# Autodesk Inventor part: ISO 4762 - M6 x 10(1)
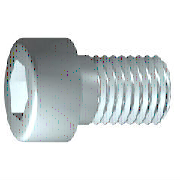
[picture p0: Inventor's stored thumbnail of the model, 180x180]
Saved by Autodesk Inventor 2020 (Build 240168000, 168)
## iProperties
IsCustomPart: 0
Created: 2019-01
Part Number: ISO 4762 - M6 x 10(1)
Material: Nerezová ocel 440C
Description: Šroub s válcovou hlavou s vnitřním šestihranem
Document SubType Name: Modeling
Standard: ISO 4762
Designer: doma
Standard Revision: Fourth edition 2004-03-01
Standards Organization: ISO
Language: cs-CZ
Size Designation: M6 x 10
Categories: <MemberInstance><Categories><Category DisplayName="Spojovací materiál" InternalName="e4da775c-781d-43d5-af7c-5136215cf5a6" Mnemonic="FSTN"><Category DisplayName
Density: 7.75 g/cm^3
Appearance: Pololeštěná
Mass: 5.18675 g
Surface Area: 5.75604 cm^2
Volume: 0.669258 cm^3
Author: doma
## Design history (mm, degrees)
sketch "Náčrt1"
  geometry: L1 (-1.333, 0)-(10, 0); L2 (10, 0)-(10, 3); L3 (10, 3)-(2.5, 3); L4 (2.5, 3)-(1.886, 3); L5 (1.886, 3)-(0, 3); L6 (0, 3)-(0, 5); L7 (0, 5)-(-6, 5); L8 (-6, 5)-(-6, 2.887); L9 (-6, 2.887)-(-3, 2.887); L10 (-3, 2.887)-(-1.333, 0); L11 (-9.2, 0)-(13.2, 0) reference; L12 (0, -1)-(0, 6) reference; L13 (2.5, 3)-(0, 3)
  constraints: 22 end point, 6 parallel, 2 collinear, 2 perpendicular, 1 horizontal, 1 point on line
  dimensions: "d1" = 7.5 distance from line of L3.end L2 (= GEL); "d2" = 0.61355 distance of L4.end L3.end (computed from GAL); "d3" = 6 distance between parallel lines of L8 L6 (= KOH); "d4" = 3 distance of L8.end L9.end (= INTI); "d5" = 60 deg angle of L10 L1; "d6" = 6 diameter of L3 L1 (= GD); "d7" = 6 diameter of L5 L1 (= BDM); "d8" = 5.7735 diameter of L9 L1 (= 1.1547 x SW); "d9" = 10 diameter of L7 L1 (= KOD); "d26" = 10 distance between parallel lines of L12 L2 (= NLG)
revolve "Těleso" sketch "Náčrt1" stored, may be unused: angle "d10" = 90 deg
sketch "Náčrt2"
  geometry: L1 (0, -7)-(0, 7) reference; L2 (-7, 0)-(7, 0) reference; L3 (2.887, 0)-(1.443, -2.5); L4 (1.443, -2.5)-(-1.443, -2.5); L5 (-1.443, -2.5)-(-2.887, 0); L6 (-2.887, 0)-(-1.443, 2.5); L7 (-1.443, 2.5)-(1.443, 2.5); L8 (1.443, 2.5)-(2.887, 0); 2 further points
  constraints: 12 end point, 1 coincident, 1 horizontal alignment, 1 point on line, 12 other
extrude "Drážka" join sketch "Náčrt2" stored distance "d11" = 10; taper "d12" = 0 deg
workplane "Work Plane1"
fillet "Fillet2" dims "d30" = 0.1 (= R)
body "Solid1"
fillet "Zaoblení1" dims "d17" = 0.6 (= RR)
feature "Závit" dims "d13" = 7.5 (= GEL), "d14" = 0
chamfer "Zkosení1" distance "d15" = 0.61345 (= -0.5 x SPD + 0.5 x GD); stored, may be unused: second distance "d16" = 0.61345 (= GUL), angle "d27" = 45 deg
other parameters: "GD" = 6 [user parameter; used in 2 equation terms], "NLG" = 10 [user parameter; used in 1 equation term], "GEL" = 7.5 [user parameter; used in 2 equation terms], "KOD" = 10 [user parameter; used in 1 equation term], "KOH" = 6 [user parameter; used in 1 equation term], "INTI" = 3 [user parameter; used in 1 equation term], "GAL" = 0.61345 (= 0.61345 x PTC) [user parameter; used in 1 equation term], "GUL" = 0.61345 (= 0.61345 x PTC) [user parameter; used in 1 equation term], "BDM" = 6 (= NND) [user parameter; used in 1 equation term], "SW" = 5 [user parameter; used in 2 equation terms], "RR" = 0.6 [user parameter; used in 1 equation term], "SPD" = 4.7731 (= NND - 1.2269 x PTC) [user parameter; used in 1 equation term], "d19" = 0, "d28" = 0, "d29" = 0, "R" = 0.1 [user parameter; used in 1 equation term], "TOA" = 30 deg [user parameter], "GD1" = 4.7731 (= THREADDIA - 1.2269 x PTC) [user parameter], "THREADDIA" = 6 [user parameter; used in 1 equation term], "FAWI" = 45 deg [user parameter], "PTC" = 1 [user parameter; used in 5 equation terms], "NND" = 6 [user parameter; used in 2 equation terms], "E0" = 5.775 (= 1.155 x SW) [user parameter]
